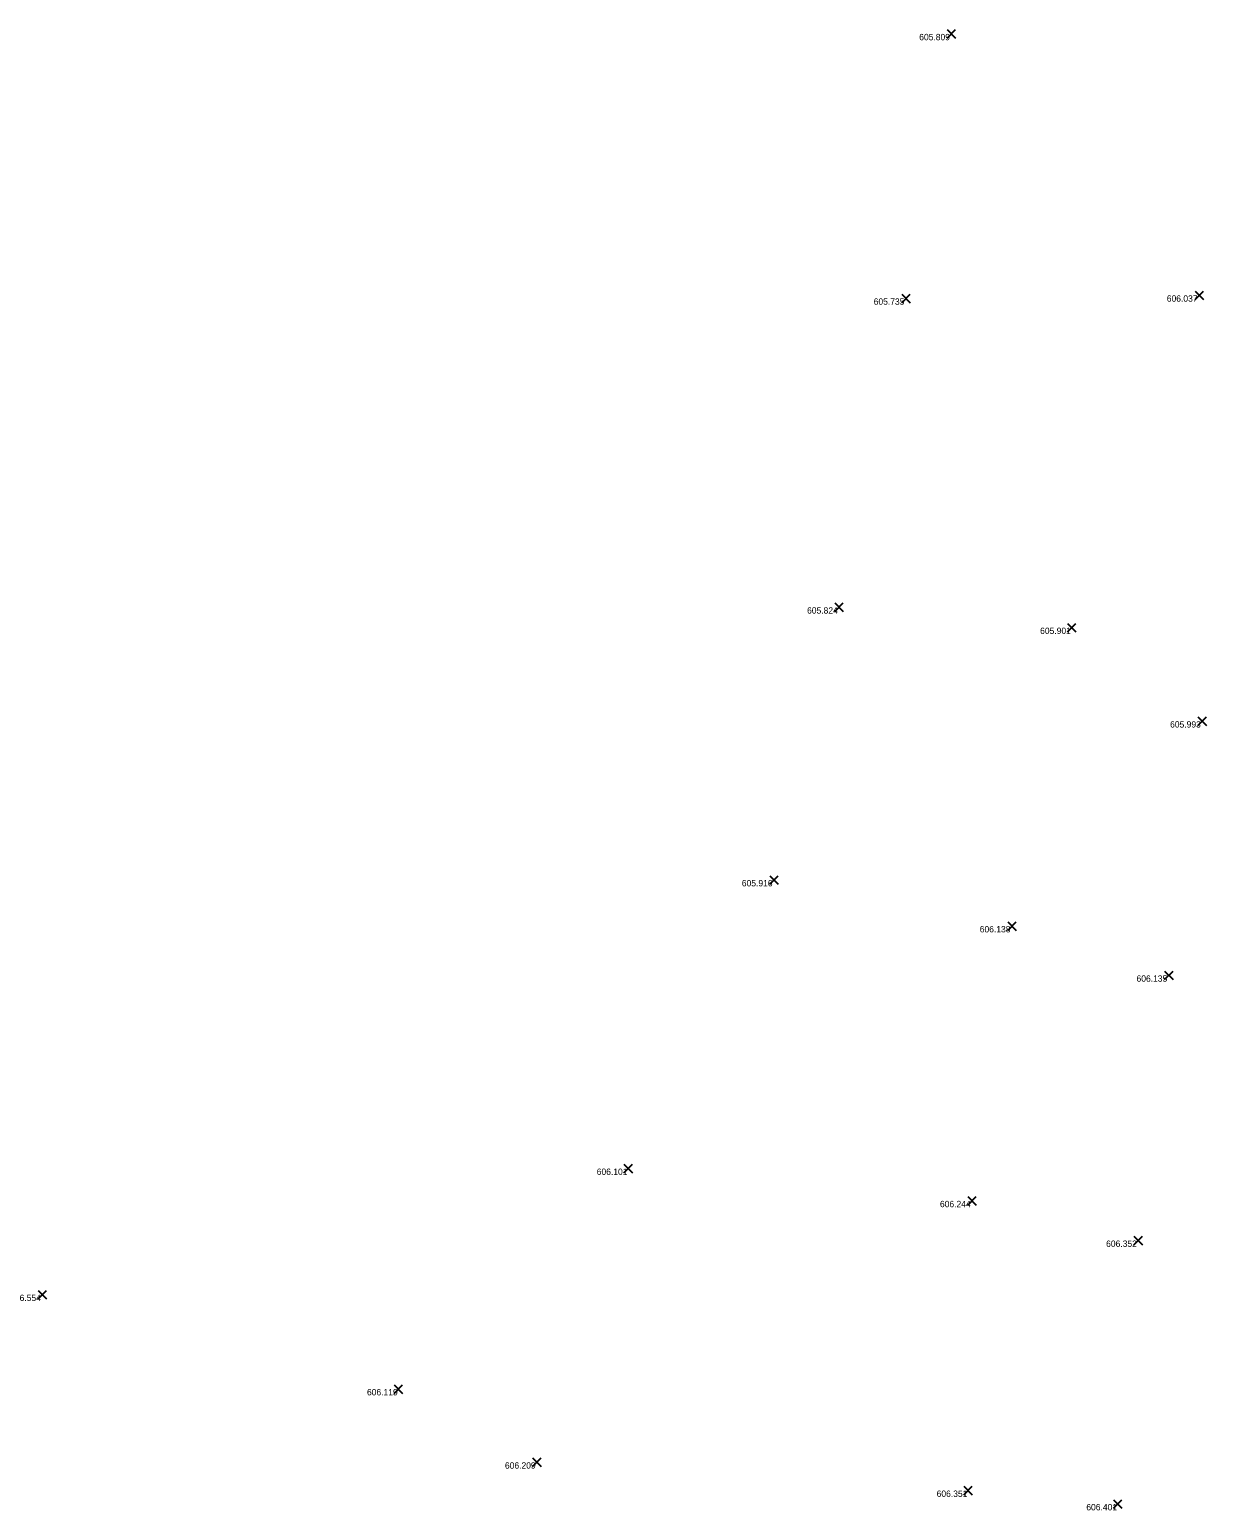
# Model space of a CAD drawing. Extents: x -2 to 1979875, y -2 to 232027.
# Drawn here: x 1978636.7 to 1978729.3, y 231463.8 to 231580.3 of the extents above; entities that cross this region are included whole.
import ezdxf

# ---------------------------------------------------------------- set-up
doc = ezdxf.new("R2010")
doc.units = 0
doc.layers.add('_CIVIL_CONSTRUCTION', color=7, linetype='Continuous')
doc.layers.add('SV_X_Random_Point', color=7, linetype='Continuous')

msp = doc.modelspace()

# ---------------------------------------------------------------- linework, layer by layer
at = {"layer": 'SV_X_Random_Point'}
for p, q in [((1978708.87, 231579.6), (1978709.53, 231580.27)), ((1978708.87, 231580.27), (1978709.53, 231579.6)), ((1978705.3, 231558.79), (1978705.97, 231559.46)), ((1978705.3, 231559.46), (1978705.97, 231558.79)), ((1978728.37, 231559.04), (1978729.04, 231559.71)), ((1978728.37, 231559.71), (1978729.04, 231559.04)), ((1978700.04, 231534.51), (1978700.7, 231535.18)), ((1978700.04, 231535.18), (1978700.7, 231534.51)), ((1978718.33, 231532.91), (1978719, 231533.57)), ((1978718.33, 231533.57), (1978719, 231532.91)), ((1978728.6, 231525.55), (1978729.26, 231526.22)), ((1978728.6, 231526.22), (1978729.26, 231525.55)), ((1978694.93, 231513.06), (1978695.6, 231513.72)), ((1978694.93, 231513.72), (1978695.6, 231513.06)), ((1978713.64, 231509.43), (1978714.3, 231510.1)), ((1978713.64, 231510.1), (1978714.3, 231509.43)), ((1978725.97, 231505.56), (1978726.64, 231506.23)), ((1978725.97, 231506.23), (1978726.64, 231505.56)), ((1978683.46, 231490.37), (1978684.12, 231491.04)), ((1978683.46, 231491.04), (1978684.12, 231490.37)), ((1978710.49, 231487.83), (1978711.16, 231488.49)), ((1978710.49, 231488.49), (1978711.16, 231487.83)), ((1978723.57, 231484.7), (1978724.24, 231485.37)), ((1978723.57, 231485.37), (1978724.24, 231484.7)), ((1978637.38, 231480.45), (1978638.04, 231481.12)), ((1978637.38, 231481.12), (1978638.04, 231480.45)), ((1978665.39, 231473.02), (1978666.05, 231473.69)), ((1978665.39, 231473.69), (1978666.05, 231473.02)), ((1978676.28, 231467.27), (1978676.95, 231467.94)), ((1978676.28, 231467.94), (1978676.95, 231467.27)), ((1978710.19, 231465.05), (1978710.85, 231465.72)), ((1978710.19, 231465.72), (1978710.85, 231465.05)), ((1978721.96, 231463.99), (1978722.62, 231464.66)), ((1978721.96, 231464.66), (1978722.62, 231463.99))]:
    msp.add_line(p, q, dxfattribs=at)

# ---------------------------------------------------------------- texts
at = {"layer": '_CIVIL_CONSTRUCTION'}
for s, p in [('605.809', (1978706.68, 231579.43)), ('605.735', (1978703.1, 231558.63)), ('606.037', (1978726.15, 231558.87)), ('605.824', (1978697.86, 231534.34)), ('605.901', (1978716.19, 231532.74)), ('605.993', (1978726.41, 231525.38)), ('605.916', (1978692.73, 231512.89)), ('606.138', (1978711.44, 231509.27)), ('606.135', (1978723.77, 231505.39)), ('606.101', (1978681.32, 231490.2)), ('606.244', (1978708.31, 231487.66)), ('606.352', (1978721.38, 231484.54)), ('606.554', (1978635.19, 231480.28)), ('606.119', (1978663.25, 231472.86)), ('606.209', (1978674.1, 231467.1)), ('606.351', (1978708.05, 231464.88)), ('606.401', (1978719.82, 231463.82))]:
    msp.add_text(s, height=0.5, dxfattribs=at).set_placement(p)

doc.saveas('drawing.dxf')
